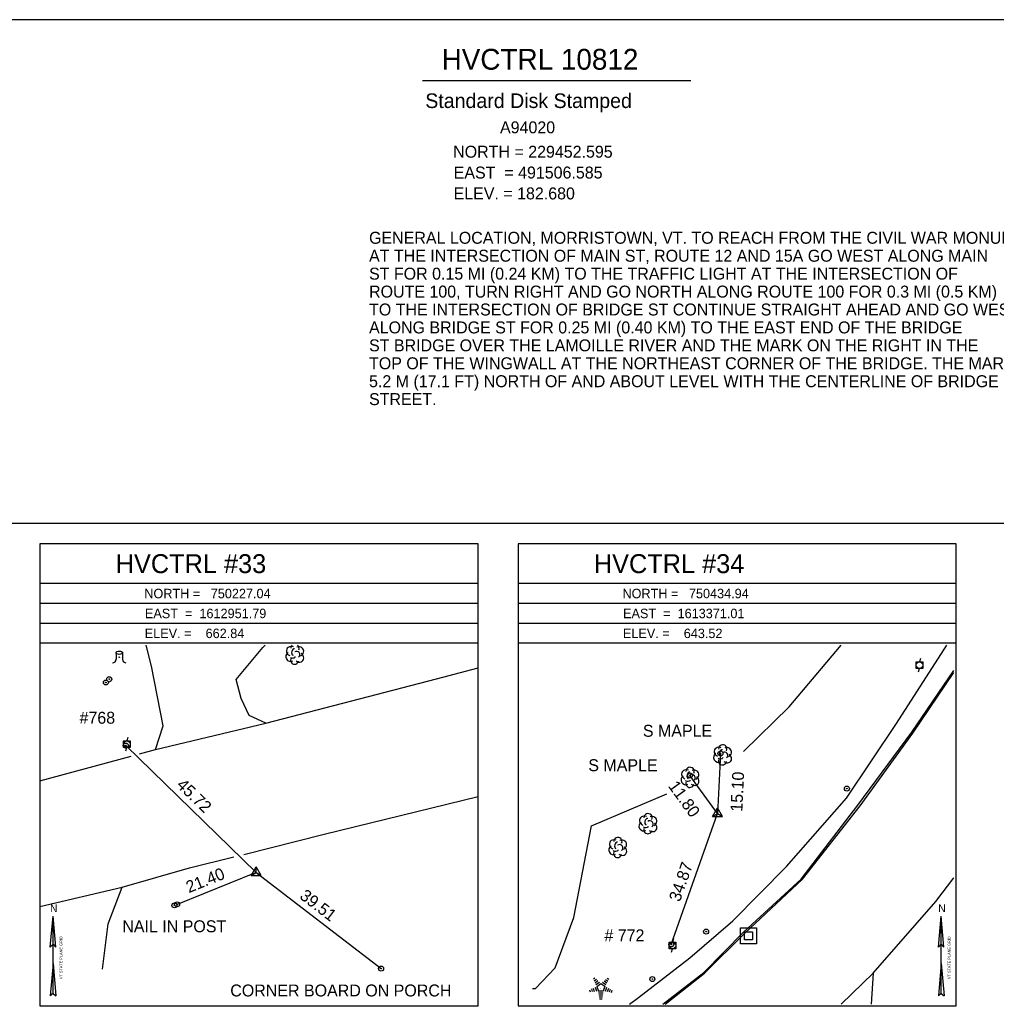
# Model space of a CAD drawing. Extents: x 1612431 to 1613071, y 750572 to 750992.
# Drawn here: x 1612701.1 to 1612946.1, y 750742 to 750992.1 of the extents above; entities that cross this region are included whole.
import ezdxf

# ---------------------------------------------------------------- set-up
doc = ezdxf.new("R2010")
doc.units = 0
for name, color, linetype in [('C_C', 7, 'Continuous'), ('CBP', 7, 'Continuous'), ('CPSM', 7, 'Continuous'), ('Default', 7, 'Continuous'), ('DS', 7, 'Continuous'), ('L_C', 7, 'Continuous'), ('LAPB', 7, 'Continuous'), ('LAWA', 7, 'Continuous'), ('Level 1', 7, 'Continuous'), ('Level 2', 7, 'Continuous'), ('Level 63', 7, 'Continuous'), ('LPST', 7, 'Continuous'), ('LSH', 7, 'Continuous'), ('LTC', 7, 'Continuous'), ('LTD', 7, 'Continuous'), ('LTS', 7, 'Continuous'), ('NBL2', 7, 'Continuous'), ('NNA_P', 7, 'Continuous'), ('PET', 7, 'Continuous'), ('RC', 7, 'Continuous'), ('RDG', 7, 'Continuous'), ('RDP', 7, 'Continuous'), ('RSW', 7, 'Continuous'), ('U_C', 7, 'Continuous'), ('UP', 7, 'Continuous'), ('UPGW', 7, 'Continuous')]:
    doc.layers.add(name, color=color, linetype=linetype)

msp = doc.modelspace()

# ---------------------------------------------------------------- linework, layer by layer
at = {"layer": 'CBP'}
for centre, radius in [((1612727.68, 750809.96), 0.625), ((1612727.68, 750809.96), 0.0833), ((1612876.93, 750807.98), 0.625), ((1612876.93, 750807.98), 0.0833), ((1612869.29, 750802.45), 0.625), ((1612869.29, 750802.45), 0.0833), ((1612740.58, 750770.09), 0.625), ((1612740.58, 750770.09), 0.0833), ((1612864.61, 750760.02), 0.625), ((1612864.61, 750760.02), 0.0833), ((1612791.76, 750753.97), 0.625), ((1612791.76, 750753.97), 0.0833)]:
    msp.add_circle(centre, radius, dxfattribs=at)
at = {"layer": 'CPSM'}
for p, q in [((1612874.97, 750792.17), (1612876.22, 750794.34)), ((1612874.97, 750792.17), (1612876.22, 750792.9)), ((1612877.47, 750792.17), (1612876.22, 750794.34)), ((1612876.22, 750792.9), (1612876.22, 750794.34)), ((1612876.22, 750792.9), (1612876.22, 750792.9)), ((1612876.22, 750792.9), (1612877.47, 750792.17)), ((1612874.97, 750792.17), (1612877.47, 750792.17)), ((1612759.19, 750777.35), (1612760.44, 750779.51)), ((1612759.19, 750777.35), (1612760.44, 750778.07)), ((1612761.69, 750777.35), (1612760.44, 750779.51)), ((1612760.44, 750778.07), (1612760.44, 750779.51)), ((1612760.44, 750778.07), (1612760.44, 750778.07)), ((1612760.44, 750778.07), (1612761.69, 750777.35)), ((1612759.19, 750777.35), (1612761.69, 750777.35))]:
    msp.add_line(p, q, dxfattribs=at)
at = {"layer": 'Default'}
for p, q in [((1612727.68, 750809.96), (1612760.44, 750778.07)), ((1612876.93, 750807.98), (1612876.22, 750792.9)), ((1612876.22, 750792.9), (1612869.29, 750802.45)), ((1612864.61, 750760.02), (1612876.22, 750792.9)), ((1612760.44, 750778.07), (1612740.58, 750770.09)), ((1612760.44, 750778.07), (1612791.76, 750753.97))]:
    msp.add_line(p, q, dxfattribs=at)
at = {"layer": 'DS'}
for p, q in [((1612881.97, 750764.2), (1612885.97, 750764.2)), ((1612881.97, 750760.2), (1612881.97, 750764.2)), ((1612882.97, 750761.2), (1612882.97, 750763.2)), ((1612882.97, 750763.2), (1612884.97, 750763.2)), ((1612884.97, 750763.2), (1612884.97, 750761.2)), ((1612885.97, 750764.2), (1612885.97, 750760.2)), ((1612885.97, 750760.2), (1612881.97, 750760.2)), ((1612884.97, 750761.2), (1612882.97, 750761.2)), ((1612883.98, 750762.2), (1612883.98, 750762.2)), ((1612883.98, 750762.2), (1612883.98, 750762.2))]:
    msp.add_line(p, q, dxfattribs=at)
at = {"layer": 'LAPB'}
msp.add_lwpolyline([(1612829.81, 750748.97), (1612830.52, 750749), (1612835.44, 750754.16), (1612840.15, 750766.77), (1612844.6, 750789.82)], dxfattribs=at)
at = {"layer": 'LAWA'}
for points in [[(1612882.75, 750808.49), (1612894.21, 750819.67), (1612907.21, 750835.19)], [(1612844.6, 750789.82), (1612863.47, 750797.87)]]:
    msp.add_lwpolyline(points, dxfattribs=at)
at = {"layer": 'Level 1'}
msp.add_line((1612802.19, 750976.88), (1612869.48, 750976.88), dxfattribs=at)
at = {"layer": 'LPST'}
for centre, radius in [((1612908.66, 750799.15), 0.625), ((1612908.66, 750799.15), 0.0833), ((1612739.89, 750769.85), 0.625), ((1612739.89, 750769.85), 0.0833), ((1612873.35, 750763.26), 0.625), ((1612873.35, 750763.26), 0.0833), ((1612859.85, 750751.34), 0.625), ((1612859.85, 750751.34), 0.0833)]:
    msp.add_circle(centre, radius, dxfattribs=at)
at = {"layer": 'LSH'}
for p, q in [((1612858.71, 750790.4), (1612858.71, 750790.4)), ((1612858.71, 750790.4), (1612858.71, 750790.4)), ((1612851.14, 750784.43), (1612851.14, 750784.43)), ((1612851.14, 750784.43), (1612851.14, 750784.43))]:
    msp.add_line(p, q, dxfattribs=at)
for centre in [(1612858.76, 750791.83), (1612851.19, 750785.86)]:
    msp.add_arc(centre, 1.05, 335.5272, 180.9563, dxfattribs=at)
for centre, major_axis, ratio, start_param, end_param in [((1612857.63, 750789.69), (0.58, -1.04), 0.959034, 3.141593, 6.283185), ((1612857.92, 750791.06), (1.21, -0.51), 0.895232, 1.570796, 4.712389), ((1612858.5, 750790.85), (-0.208, -0.792), 0.645439, 3.141593, 6.283185), ((1612859.21, 750790.23), (-0.5, 0.667), 0.989748, 3.141593, 6.283185), ((1612859.71, 750789.56), (-1.09, 0.79), 0.841452, 1.570796, 4.712389), ((1612859.75, 750790.98), (-1.14, -0.48), 0.949671, 1.570796, 4.712389), ((1612858.71, 750788.9), (0.26, 1.06), 0.942809, 1.570796, 4.712389), ((1612858.25, 750789.65), (-0.625, -0.083), 0.423636, 0, 3.141593), ((1612850.35, 750785.1), (1.21, -0.51), 0.895232, 1.570796, 4.712389), ((1612850.93, 750784.89), (-0.208, -0.792), 0.645439, 3.141593, 6.283185), ((1612851.64, 750784.26), (-0.5, 0.667), 0.989748, 3.141593, 6.283185), ((1612852.18, 750785.01), (-1.14, -0.48), 0.949671, 1.570796, 4.712389), ((1612850.06, 750783.72), (0.58, -1.04), 0.959034, 3.141593, 6.283185), ((1612851.14, 750782.93), (0.26, 1.06), 0.942809, 1.570796, 4.712389), ((1612850.68, 750783.68), (-0.625, -0.083), 0.423636, 0, 3.141593), ((1612852.14, 750783.6), (-1.09, 0.79), 0.841452, 1.570796, 4.712389)]:
    msp.add_ellipse(centre, major_axis=major_axis, ratio=ratio, start_param=start_param, end_param=end_param, dxfattribs=at)
at = {"layer": 'LTC'}
for p, q in [((1612845.07, 750751.36), (1612845.42, 750751.62)), ((1612845.28, 750750.89), (1612845.81, 750751.28)), ((1612845.49, 750750.43), (1612846.19, 750750.94)), ((1612845.7, 750749.96), (1612846.58, 750750.6)), ((1612845.92, 750749.51), (1612846.93, 750750.24)), ((1612846.93, 750750.24), (1612847.93, 750749.52)), ((1612847.35, 750750.55), (1612848.16, 750749.97)), ((1612847.73, 750750.9), (1612848.4, 750750.41)), ((1612848.1, 750751.25), (1612848.65, 750750.85)), ((1612848.47, 750751.6), (1612848.89, 750751.3)), ((1612844.1, 750748.64), (1612844.25, 750748.17)), ((1612844.56, 750748.86), (1612844.77, 750748.2)), ((1612845.01, 750749.07), (1612845.28, 750748.24)), ((1612845.47, 750749.29), (1612845.8, 750748.27)), ((1612845.92, 750749.51), (1612846.31, 750748.31)), ((1612847.54, 750748.31), (1612846.31, 750748.31)), ((1612847.5, 750747.81), (1612846.36, 750747.81)), ((1612847.93, 750749.52), (1612847.54, 750748.31)), ((1612848.37, 750749.25), (1612848.03, 750748.21)), ((1612848.81, 750749), (1612848.53, 750748.11)), ((1612849.26, 750748.75), (1612849.02, 750748.02)), ((1612849.7, 750748.5), (1612849.52, 750747.92)), ((1612847.42, 750747.31), (1612846.43, 750747.31)), ((1612847.33, 750746.81), (1612846.5, 750746.81)), ((1612847.25, 750746.31), (1612846.58, 750746.31))]:
    msp.add_line(p, q, dxfattribs=at)
at = {"layer": 'LTD'}
for p, q in [((1612770.08, 750832.96), (1612770.08, 750832.96)), ((1612770.08, 750832.96), (1612770.08, 750832.96)), ((1612877.46, 750807.67), (1612877.46, 750807.67)), ((1612877.46, 750807.67), (1612877.46, 750807.67)), ((1612869.27, 750802.02), (1612869.27, 750802.02)), ((1612869.27, 750802.02), (1612869.27, 750802.02))]:
    msp.add_line(p, q, dxfattribs=at)
for centre, start, end in [((1612770.13, 750834.39), 130.8505, 180.9563), ((1612770.13, 750834.39), 335.5272, 49.1495), ((1612877.51, 750809.11), 335.5272, 180.9563), ((1612869.32, 750803.45), 335.5272, 180.9563)]:
    msp.add_arc(centre, 1.05, start, end, dxfattribs=at)
for centre, major_axis, ratio, start_param, end_param in [((1612769, 750832.25), (0.58, -1.04), 0.959034, 3.141593, 6.283185), ((1612769.29, 750833.62), (1.21, -0.51), 0.895232, 1.570796, 4.712389), ((1612769.87, 750833.42), (-0.208, -0.792), 0.645439, 3.141593, 6.283185), ((1612770.58, 750832.79), (-0.5, 0.667), 0.989748, 3.141593, 6.283185), ((1612771.08, 750832.12), (-1.09, 0.79), 0.841452, 1.570796, 4.712389), ((1612771.12, 750833.54), (-1.14, -0.48), 0.949671, 1.570796, 4.712389), ((1612770.08, 750831.46), (0.26, 1.06), 0.942809, 1.570796, 4.712389), ((1612769.62, 750832.21), (-0.625, -0.083), 0.423636, 0, 3.141593), ((1612876.38, 750806.96), (0.58, -1.04), 0.959034, 3.141593, 6.283185), ((1612876.67, 750808.34), (1.21, -0.51), 0.895232, 1.570796, 4.712389), ((1612877.25, 750808.13), (-0.208, -0.792), 0.645439, 3.141593, 6.283185), ((1612877.96, 750807.51), (-0.5, 0.667), 0.989748, 3.141593, 6.283185), ((1612878.46, 750806.84), (-1.09, 0.79), 0.841452, 1.570796, 4.712389), ((1612878.5, 750808.26), (-1.14, -0.48), 0.949671, 1.570796, 4.712389), ((1612877.46, 750806.17), (0.26, 1.06), 0.942809, 1.570796, 4.712389), ((1612877, 750806.92), (-0.625, -0.083), 0.423636, 0, 3.141593), ((1612868.48, 750802.68), (1.21, -0.51), 0.895232, 1.570796, 4.712389), ((1612869.06, 750802.47), (-0.208, -0.792), 0.645439, 3.141593, 6.283185), ((1612869.77, 750801.85), (-0.5, 0.667), 0.989748, 3.141593, 6.283185), ((1612870.31, 750802.6), (-1.14, -0.48), 0.949671, 1.570796, 4.712389), ((1612868.19, 750801.31), (0.58, -1.04), 0.959034, 3.141593, 6.283185), ((1612869.27, 750800.52), (0.26, 1.06), 0.942809, 1.570796, 4.712389), ((1612868.81, 750801.27), (-0.625, -0.083), 0.423636, 0, 3.141593), ((1612870.27, 750801.18), (-1.09, 0.79), 0.841452, 1.570796, 4.712389)]:
    msp.add_ellipse(centre, major_axis=major_axis, ratio=ratio, start_param=start_param, end_param=end_param, dxfattribs=at)
at = {"layer": 'LTS'}
for p, q in [((1612725.24, 750833.26), (1612725.24, 750831.59)), ((1612726.9, 750833.09), (1612726.9, 750833.26)), ((1612726.9, 750833.26), (1612726.9, 750831.59)), ((1612726.07, 750832.11), (1612726.07, 750832.11)), ((1612726.07, 750832.11), (1612726.07, 750832.11)), ((1612726.07, 750832.09), (1612726.07, 750832.09))]:
    msp.add_line(p, q, dxfattribs=at)
msp.add_circle((1612726.07, 750832.11), 0.0833, dxfattribs=at)
for centre, start, end in [((1612724.4, 750831.59), 270, 360), ((1612727.74, 750831.59), 180, 270)]:
    msp.add_arc(centre, 0.833, start, end, dxfattribs=at)
msp.add_ellipse((1612726.07, 750833.26), major_axis=(-0.833, 0), ratio=0.5, dxfattribs=at)
at = {"layer": 'NBL2'}
for p, q in [((1612431.13, 750865.8), (1613071.13, 750865.8)), ((1612816.13, 750850.63), (1612706.13, 750850.63)), ((1612936.13, 750850.63), (1612826.13, 750850.63)), ((1612816.13, 750845.63), (1612706.13, 750845.63)), ((1612936.13, 750845.63), (1612826.13, 750845.63)), ((1612816.13, 750840.63), (1612706.13, 750840.63)), ((1612936.13, 750840.63), (1612826.13, 750840.63)), ((1612816.13, 750835.63), (1612706.13, 750835.63)), ((1612936.13, 750835.63), (1612826.13, 750835.63))]:
    msp.add_line(p, q, dxfattribs=at)
for points in [[(1612431.13, 750572.13), (1613071.13, 750572.13), (1613071.13, 750992.13), (1612431.13, 750992.13)], [(1612706.13, 750744.63), (1612816.13, 750744.63), (1612816.13, 750860.63), (1612706.13, 750860.63)], [(1612826.13, 750744.63), (1612936.13, 750744.63), (1612936.13, 750860.63), (1612826.13, 750860.63)]]:
    msp.add_lwpolyline(points, close=True, dxfattribs=at)
at = {"layer": 'NNA_P'}
for p, q in [((1612708.74, 750759.34), (1612709.43, 750767.13)), ((1612709.44, 750747.75), (1612709.43, 750767.13)), ((1612710.13, 750759.34), (1612709.43, 750767.13)), ((1612931.65, 750759.34), (1612932.34, 750767.13)), ((1612932.35, 750747.75), (1612932.34, 750767.13)), ((1612933.04, 750759.34), (1612932.34, 750767.13)), ((1612708.74, 750759.34), (1612709.44, 750760.1)), ((1612710.13, 750759.34), (1612709.44, 750760.1)), ((1612931.65, 750759.34), (1612932.34, 750760.1)), ((1612933.04, 750759.34), (1612932.34, 750760.1)), ((1612709.44, 750755.28), (1612708.72, 750747.12)), ((1612709.44, 750755.28), (1612710.16, 750747.12)), ((1612932.35, 750755.28), (1612931.63, 750747.12)), ((1612932.34, 750755.28), (1612933.07, 750747.12)), ((1612709.44, 750747.75), (1612708.72, 750747.12)), ((1612709.44, 750747.75), (1612710.16, 750747.12)), ((1612932.35, 750747.75), (1612931.63, 750747.12)), ((1612932.35, 750747.75), (1612933.07, 750747.12))]:
    msp.add_line(p, q, dxfattribs=at)
at = {"layer": 'PET'}
for points in [[(1612731.17, 750807.85), (1612735.18, 750808.93), (1612762.88, 750815.59), (1612805.65, 750826.73), (1612816.13, 750829.46)], [(1612863.08, 750745.02), (1612872.93, 750752.79), (1612883.02, 750762.82), (1612897.56, 750776.4), (1612912, 750794.84), (1612925.22, 750813.05), (1612935.55, 750828.28)], [(1612706.13, 750801.11), (1612729.06, 750807.28)], [(1612757.3, 750782.65), (1612777.52, 750787.73), (1612816.13, 750797.14)], [(1612706.13, 750769.58), (1612726.77, 750774.44), (1612743.7, 750779.24), (1612754.83, 750782.03)], [(1612907.25, 750745.02), (1612915.27, 750752.86), (1612931, 750770.78), (1612935.55, 750776.77)], [(1612721.88, 750753.8), (1612723.26, 750765.23), (1612726.77, 750774.44)]]:
    msp.add_lwpolyline(points, dxfattribs=at)
at = {"layer": 'RC'}
msp.add_lwpolyline([(1612862.49, 750745.02), (1612872.75, 750752.99), (1612882.79, 750763.2), (1612897.21, 750776.44), (1612911.43, 750795.02), (1612924.99, 750813.31), (1612935.55, 750828.77)], dxfattribs=at)
at = {"layer": 'RDG'}
msp.add_lwpolyline([(1612915.27, 750752.86), (1612914.78, 750745.02)], dxfattribs=at)
at = {"layer": 'RDP'}
for points in [[(1612735.18, 750808.93), (1612737.09, 750814.88), (1612734.12, 750829.93), (1612732.79, 750835.18)], [(1612762.88, 750815.59), (1612758.7, 750817.53), (1612756.68, 750821.78), (1612755.37, 750826.53), (1612762.07, 750834.56), (1612762.64, 750835.18)]]:
    msp.add_lwpolyline(points, dxfattribs=at)
at = {"layer": 'RSW'}
msp.add_lwpolyline([(1612854.1, 750745.02), (1612856.41, 750746.69), (1612869.29, 750756.68), (1612880.04, 750765.92), (1612893.53, 750779.62), (1612908.61, 750796.74), (1612921.16, 750815.47), (1612933.74, 750835.19)], dxfattribs=at)
at = {"layer": 'UP'}
for p, q in [((1612926.04, 750829.32), (1612926.04, 750830.99)), ((1612926.04, 750830.99), (1612927.7, 750830.99)), ((1612927.12, 750831.82), (1612926.87, 750830.99)), ((1612927.7, 750830.99), (1612927.7, 750829.32)), ((1612927.7, 750829.32), (1612926.04, 750829.32)), ((1612926.62, 750828.49), (1612926.87, 750829.32)), ((1612926.87, 750830.15), (1612926.87, 750830.15)), ((1612727.13, 750809.48), (1612727.13, 750811.15)), ((1612727.13, 750811.15), (1612728.8, 750811.15)), ((1612728.21, 750811.98), (1612727.96, 750811.15)), ((1612727.96, 750810.32), (1612727.96, 750810.32)), ((1612728.8, 750811.15), (1612728.8, 750809.48)), ((1612728.8, 750809.48), (1612727.13, 750809.48)), ((1612727.71, 750808.65), (1612727.96, 750809.48)), ((1612864.09, 750758.91), (1612864.09, 750760.57)), ((1612864.09, 750760.57), (1612865.76, 750760.57)), ((1612865.17, 750761.41), (1612864.92, 750760.57)), ((1612865.76, 750760.57), (1612865.76, 750758.91)), ((1612865.76, 750758.91), (1612864.09, 750758.91)), ((1612864.67, 750758.07), (1612864.92, 750758.91)), ((1612864.92, 750759.74), (1612864.92, 750759.74))]:
    msp.add_line(p, q, dxfattribs=at)
for centre in [(1612926.87, 750830.15), (1612727.96, 750810.32), (1612864.92, 750759.74)]:
    msp.add_circle(centre, 0.833, dxfattribs=at)
at = {"layer": 'UPGW'}
for centre, radius in [((1612722.7, 750825.79), 0.625), ((1612722.7, 750825.79), 0.0833), ((1612723.55, 750826.62), 0.625), ((1612723.55, 750826.62), 0.0833)]:
    msp.add_circle(centre, radius, dxfattribs=at)

# ---------------------------------------------------------------- texts
at = {"layer": 'C_C'}
for s, p in [('NAIL IN POST', (1612726.82, 750763.09)), ('CORNER BOARD ON PORCH', (1612753.92, 750746.97))]:
    msp.add_text(s, height=3, dxfattribs=at).set_placement(p)
at = {"layer": 'Default'}
for s, rotation, p in [('15.10', 87.331, (1612882.43, 750793.31)), ('45.72', 315.7759, (1612740.24, 750799.83)), ('11.80', 305.9403, (1612863.69, 750799.77)), ('34.87', 70.5431, (1612866.74, 750770.55)), ('21.40', 21.8838, (1612743.53, 750772.89)), ('39.51', 322.4226, (1612771.12, 750771.75))]:
    msp.add_text(s, height=3, rotation=rotation, dxfattribs=at).set_placement(p)
at = {"layer": 'L_C'}
for p in [(1612857.47, 750812.17), (1612843.78, 750803.53)]:
    msp.add_text('S MAPLE', height=3, dxfattribs=at).set_placement(p)
at = {"layer": 'Level 1'}
msp.add_text('Standard Disk Stamped', height=3.6714, dxfattribs=at).set_placement((1612802.86, 750970.01))
at = {"layer": 'Level 2'}
for s, p in [('GENERAL LOCATION, MORRISTOWN, VT. TO REACH FROM THE CIVIL WAR MONUMENT', (1612788.75, 750935.93)), ('AT THE INTERSECTION OF MAIN ST, ROUTE 12 AND 15A GO WEST ALONG MAIN', (1612788.75, 750931.43)), ('ST FOR 0.15 MI (0.24 KM) TO THE TRAFFIC LIGHT AT THE INTERSECTION OF', (1612788.75, 750926.93)), ('ROUTE 100, TURN RIGHT AND GO NORTH ALONG ROUTE 100 FOR 0.3 MI (0.5 KM)', (1612788.75, 750922.43)), ('TO THE INTERSECTION OF BRIDGE ST CONTINUE STRAIGHT AHEAD AND GO WEST', (1612788.75, 750917.93)), ('ALONG BRIDGE ST FOR 0.25 MI (0.40 KM) TO THE EAST END OF THE BRIDGE', (1612788.75, 750913.43)), ('ST BRIDGE OVER THE LAMOILLE RIVER AND THE MARK ON THE RIGHT IN THE', (1612788.75, 750908.93)), ('TOP OF THE WINGWALL AT THE NORTHEAST CORNER OF THE BRIDGE. THE MARK IS', (1612788.75, 750904.43)), ('5.2 M (17.1 FT) NORTH OF AND ABOUT LEVEL WITH THE CENTERLINE OF BRIDGE', (1612788.75, 750899.93)), ('STREET.', (1612788.75, 750895.43))]:
    msp.add_text(s, height=3, dxfattribs=at).set_placement(p)
at = {"layer": 'Level 63'}
for s, height, p in [('HVCTRL 10812  ', 5.2317, (1612806.96, 750979.63)), ('A94020                 ', 3, (1612821.62, 750963.66)), ('NORTH = 229452.595 ', 3, (1612809.86, 750957.54)), ('EAST  = 491506.585 ', 3, (1612809.99, 750952.31)), ('ELEV. = 182.680    ', 3, (1612809.96, 750947.07))]:
    msp.add_text(s, height=height, dxfattribs=at).set_placement(p)
at = {"layer": 'LTC'}
msp.add_text('.', height=1.04, rotation=270, dxfattribs=at).set_placement((1612846.82, 750749.26))
at = {"layer": 'NBL2'}
for s, height, p in [('     HVCTRL #33    ', 4.75, (1612716.34, 750853.25)), ('     HVCTRL #34    ', 4.75, (1612836.34, 750853.25)), ('NORTH =   750227.04 ', 2.375, (1612732.35, 750846.94)), ('NORTH =   750434.94 ', 2.375, (1612852.35, 750846.94)), ('EAST  =  1612951.79 ', 2.375, (1612732.5, 750841.94)), ('EAST  =  1613371.01 ', 2.375, (1612852.5, 750841.94)), ('ELEV. =    662.84   ', 2.375, (1612732.46, 750836.94)), ('ELEV. =    643.52   ', 2.375, (1612852.46, 750836.94))]:
    msp.add_text(s, height=height, dxfattribs=at).set_placement(p)
at = {"layer": 'NNA_P'}
for p in [(1612708.67, 750768.14), (1612931.58, 750768.14)]:
    msp.add_text('N', height=1.97, dxfattribs=at).set_placement(p)
for p in [(1612711.79, 750751.32), (1612934.7, 750751.32)]:
    msp.add_text('VT STATE PLANE GRID', height=0.7, rotation=90.0204, dxfattribs=at).set_placement(p)
at = {"layer": 'U_C'}
for s, p in [('#768', (1612716.09, 750815.44)), ('# 772', (1612847.82, 750760.82))]:
    msp.add_text(s, height=3, dxfattribs=at).set_placement(p)

doc.saveas('drawing.dxf')
